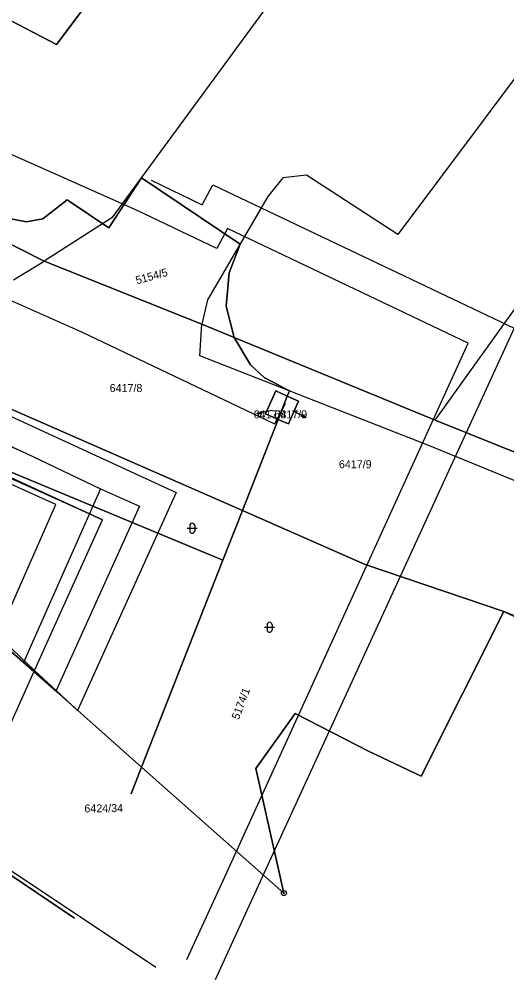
# Model space of a CAD drawing. Extents: x -400488 to -400124, y -1251493 to -1251223.
# Drawn here: x -400431 to -400401.8, y -1251493.2 to -1251435.6 of the extents above; entities that cross this region are included whole.
import ezdxf

# ---------------------------------------------------------------- set-up
doc = ezdxf.new("R2010")
doc.units = 0
doc.layers.add('Level 63', color=7, linetype='Continuous')

msp = doc.modelspace()

# ---------------------------------------------------------------- linework, layer by layer
at = {"layer": 'Level 63'}
for p, q in [((-400398.73, -1251410.99), (-400425.47, -1251447.5)), ((-400411.33, -1251413.87), (-400428.79, -1251437.09)), ((-400428.79, -1251437.09), (-400411.33, -1251413.87)), ((-400390.33, -1251424.43), (-400408.31, -1251448.5)), ((-400406.06, -1251459.62), (-400382.37, -1251426.48)), ((-400428.79, -1251437.09), (-400431.55, -1251435.66)), ((-400431.55, -1251435.66), (-400428.79, -1251437.09)), ((-400423.96, -1251447.06), (-400440.55, -1251439.68)), ((-400467.34, -1251442.9), (-400421.61, -1251463.97)), ((-400423.7, -1251445.09), (-400425.65, -1251448.09)), ((-400425.65, -1251448.09), (-400423.7, -1251445.09)), ((-400417.78, -1251449.07), (-400423.7, -1251445.09)), ((-400423.7, -1251445.09), (-400417.78, -1251449.07)), ((-400423.12, -1251445.24), (-400420.05, -1251446.71)), ((-400415.21, -1251445.09), (-400416.11, -1251446.21)), ((-400413.8, -1251444.93), (-400415.21, -1251445.09)), ((-400408.31, -1251448.5), (-400413.8, -1251444.93)), ((-400429.53, -1251450.09), (-400438.81, -1251445.43)), ((-400438.81, -1251445.43), (-400429.53, -1251450.09)), ((-400420.05, -1251446.71), (-400419.41, -1251445.51)), ((-400419.41, -1251445.51), (-400401.33, -1251454.11)), ((-400428.15, -1251446.41), (-400429.62, -1251447.56)), ((-400429.62, -1251447.56), (-400428.15, -1251446.41)), ((-400425.65, -1251448.09), (-400428.15, -1251446.41)), ((-400428.15, -1251446.41), (-400425.65, -1251448.09)), ((-400416.11, -1251446.21), (-400419.73, -1251452.41)), ((-400459.53, -1251446.7), (-400417.64, -1251465.05)), ((-400417.64, -1251465.05), (-400459.53, -1251446.7)), ((-400443.83, -1251446.98), (-400427.3, -1251454.33)), ((-400430.6, -1251447.73), (-400431.73, -1251447.52)), ((-400431.73, -1251447.52), (-400430.6, -1251447.73)), ((-400429.62, -1251447.56), (-400430.6, -1251447.73)), ((-400430.6, -1251447.73), (-400429.62, -1251447.56)), ((-400425.47, -1251447.5), (-400429.53, -1251450.09)), ((-400419.18, -1251449.33), (-400423.96, -1251447.06)), ((-400426.03, -1251465.61), (-400465.01, -1251447.65)), ((-400418.54, -1251448.13), (-400419.18, -1251449.33)), ((-400404.08, -1251455.01), (-400418.54, -1251448.13)), ((-400458.99, -1251448.58), (-400430.64, -1251461.6)), ((-400418.44, -1251450.8), (-400417.78, -1251449.07)), ((-400417.78, -1251449.07), (-400418.44, -1251450.8)), ((-400431.38, -1251451.21), (-400429.53, -1251450.09)), ((-400420.08, -1251453.86), (-400429.53, -1251450.09)), ((-400429.53, -1251450.09), (-400420.08, -1251453.86)), ((-400418.62, -1251452.78), (-400418.44, -1251450.8)), ((-400418.44, -1251450.8), (-400418.62, -1251452.78)), ((-400419.73, -1251452.41), (-400420.08, -1251453.86)), ((-400418.14, -1251454.66), (-400418.62, -1251452.78)), ((-400418.62, -1251452.78), (-400418.14, -1251454.66)), ((-400452.81, -1251453.27), (-400426.03, -1251465.61)), ((-400420.19, -1251455.76), (-400420.08, -1251453.86)), ((-400418.14, -1251454.66), (-400420.08, -1251453.86)), ((-400420.08, -1251453.86), (-400418.14, -1251454.66)), ((-400447.11, -1251454.28), (-400430.64, -1251461.6)), ((-400427.3, -1251454.33), (-400415.72, -1251459.84)), ((-400401.33, -1251454.11), (-400417.35, -1251488.99)), ((-400418.89, -1251487.45), (-400404.08, -1251455.01)), ((-400406.06, -1251459.62), (-400418.14, -1251454.66)), ((-400418.14, -1251454.66), (-400417.15, -1251456.3)), ((-400418.14, -1251454.66), (-400406.06, -1251459.62)), ((-400417.15, -1251456.3), (-400418.14, -1251454.66)), ((-400426.03, -1251465.61), (-400448.55, -1251455.5)), ((-400428.83, -1251464.68), (-400447.93, -1251456.1)), ((-400428.83, -1251464.68), (-400447.93, -1251456.1)), ((-400406.5, -1251461.12), (-400420.19, -1251455.76)), ((-400417.15, -1251456.3), (-400416.33, -1251457.07)), ((-400416.33, -1251457.07), (-400417.15, -1251456.3)), ((-400416.33, -1251457.07), (-400414.82, -1251457.86)), ((-400414.82, -1251457.86), (-400416.33, -1251457.07)), ((-400416.25, -1251459.24), (-400415.64, -1251457.87)), ((-400415.64, -1251457.87), (-400416.25, -1251459.24)), ((-400415.64, -1251457.87), (-400414.95, -1251458.18)), ((-400414.95, -1251458.18), (-400415.64, -1251457.87)), ((-400414.82, -1251457.86), (-400414.95, -1251458.18)), ((-400414.95, -1251458.18), (-400414.82, -1251457.86)), ((-400415.49, -1251459.58), (-400414.95, -1251458.18)), ((-400414.95, -1251458.18), (-400415.49, -1251459.58)), ((-400414.95, -1251458.18), (-400414.27, -1251458.48)), ((-400414.27, -1251458.48), (-400414.95, -1251458.18)), ((-400414.27, -1251458.48), (-400414.88, -1251459.85)), ((-400414.88, -1251459.85), (-400414.27, -1251458.48)), ((-400415.87, -1251459.04), (-400416.751, -1251459.226)), ((-400416.469, -1251459.105), (-400416.751, -1251459.226)), ((-400415.08, -1251458.64), (-400415.72, -1251459.84)), ((-400414.63, -1251459.04), (-400413.84, -1251459.472)), ((-400415.49, -1251459.58), (-400417.64, -1251465.05)), ((-400417.64, -1251465.05), (-400415.49, -1251459.58)), ((-400416.751, -1251459.226), (-400416.445, -1251459.223)), ((-400415.49, -1251459.58), (-400416.25, -1251459.24)), ((-400416.25, -1251459.24), (-400415.49, -1251459.58)), ((-400414.88, -1251459.85), (-400415.49, -1251459.58)), ((-400415.49, -1251459.58), (-400414.88, -1251459.85)), ((-400414.132, -1251459.38), (-400413.84, -1251459.472)), ((-400413.84, -1251459.472), (-400414.075, -1251459.275)), ((-400370.19, -1251474.16), (-400406.06, -1251459.62)), ((-400406.06, -1251459.62), (-400370.19, -1251474.16)), ((-400437.33, -1251460.34), (-400418.81, -1251468.02)), ((-400418.81, -1251468.02), (-400437.33, -1251460.34)), ((-400358.48, -1251480.87), (-400406.5, -1251461.12)), ((-400430.64, -1251461.6), (-400426.15, -1251463.74)), ((-400430.64, -1251461.6), (-400426.15, -1251463.74)), ((-400426.15, -1251463.74), (-400430.77, -1251474.16)), ((-400426.15, -1251463.74), (-400423.82, -1251464.79)), ((-400421.61, -1251463.97), (-400427.53, -1251477.04)), ((-400432.39, -1251472.74), (-400428.83, -1251464.68)), ((-400432.39, -1251472.74), (-400428.83, -1251464.68)), ((-400423.82, -1251464.79), (-400428.82, -1251475.84)), ((-400418.81, -1251468.02), (-400417.64, -1251465.05)), ((-400417.64, -1251465.05), (-400418.81, -1251468.02)), ((-400417.64, -1251465.05), (-400410.26, -1251468.29)), ((-400410.26, -1251468.29), (-400417.64, -1251465.05)), ((-400439.63, -1251465.54), (-400428.8, -1251475.91)), ((-400428.8, -1251475.91), (-400439.63, -1251465.54)), ((-400430.11, -1251474.65), (-400426.03, -1251465.61)), ((-400420.8, -1251465.96), (-400420.8, -1251466.26)), ((-400420.5, -1251465.96), (-400420.5, -1251466.26)), ((-400428.8, -1251475.91), (-400439.88, -1251466.11)), ((-400439.88, -1251466.11), (-400428.8, -1251475.91)), ((-400420.95, -1251466.11), (-400420.35, -1251466.11)), ((-400418.81, -1251468.02), (-400423.69, -1251480.43)), ((-400423.69, -1251480.43), (-400418.81, -1251468.02)), ((-400410.26, -1251468.29), (-400401.94, -1251471.11)), ((-400401.94, -1251471.11), (-400410.26, -1251468.29)), ((-400406.9, -1251480.97), (-400401.94, -1251471.11)), ((-400401.94, -1251471.11), (-400406.9, -1251480.97)), ((-400401.94, -1251471.11), (-400391.59, -1251475.88)), ((-400368.83, -1251484.14), (-400401.94, -1251471.11)), ((-400391.59, -1251475.88), (-400401.94, -1251471.11)), ((-400416.31, -1251472.05), (-400415.71, -1251472.05)), ((-400416.16, -1251471.9), (-400416.16, -1251472.2)), ((-400415.86, -1251471.9), (-400415.86, -1251472.2)), ((-400438.13, -1251492.39), (-400430.11, -1251474.65)), ((-400430.11, -1251474.65), (-400428.82, -1251475.84)), ((-400427.53, -1251477.04), (-400430.11, -1251474.65)), ((-400428.82, -1251475.84), (-400427.53, -1251477.04)), ((-400423.69, -1251480.43), (-400428.8, -1251475.91)), ((-400428.8, -1251475.91), (-400423.69, -1251480.43)), ((-400416.83, -1251480.52), (-400414.48, -1251477.21)), ((-400414.48, -1251477.21), (-400416.83, -1251480.52)), ((-400414.48, -1251477.21), (-400410.03, -1251479.49)), ((-400410.03, -1251479.49), (-400414.48, -1251477.21)), ((-400410.03, -1251479.49), (-400406.9, -1251480.97)), ((-400406.9, -1251480.97), (-400410.03, -1251479.49)), ((-400424.32, -1251482.04), (-400423.69, -1251480.43)), ((-400423.69, -1251480.43), (-400424.32, -1251482.04)), ((-400415.15, -1251487.99), (-400423.69, -1251480.43)), ((-400423.69, -1251480.43), (-400415.15, -1251487.99)), ((-400415.15, -1251487.99), (-400416.83, -1251480.52)), ((-400416.83, -1251480.52), (-400415.15, -1251487.99)), ((-400437.02, -1251483.22), (-400427.72, -1251489.49)), ((-400427.72, -1251489.49), (-400437.02, -1251483.22)), ((-400434.89, -1251484.39), (-400422.83, -1251492.43)), ((-400420.97, -1251491.98), (-400418.89, -1251487.45)), ((-400417.35, -1251488.99), (-400419.28, -1251493.19))]:
    msp.add_line(p, q, dxfattribs=at)
for radius in [0.15, 0.15, 0.03, 0.03]:
    msp.add_circle((-400415.15, -1251487.99), radius, dxfattribs=at)
for centre, start, end in [((-400420.65, -1251465.96), 0, 180), ((-400420.65, -1251466.26), 180, 0), ((-400416.01, -1251471.9), 0, 180), ((-400416.01, -1251472.2), 180, 0)]:
    msp.add_arc(centre, 0.15, start, end, dxfattribs=at)

# ---------------------------------------------------------------- texts
for s, rotation, p in [('5154/5', 15.35, (-400423.97, -1251451.484)), ('5174/1', 69.33, (-400417.855, -1251477.627)), ('6424/34', 0.77, (-400427.119, -1251483.159))]:
    msp.add_text(s, height=0.48, rotation=rotation, dxfattribs=at).set_placement(p)
for s, p in [('6417/8', (-400425.604, -1251457.94)), ('6417/8', (-400416.964, -1251459.52)), ('6417/9', (-400415.716, -1251459.52)), ('6417/9', (-400411.846, -1251462.51))]:
    msp.add_text(s, height=0.48, dxfattribs=at).set_placement(p)

doc.saveas('drawing.dxf')
